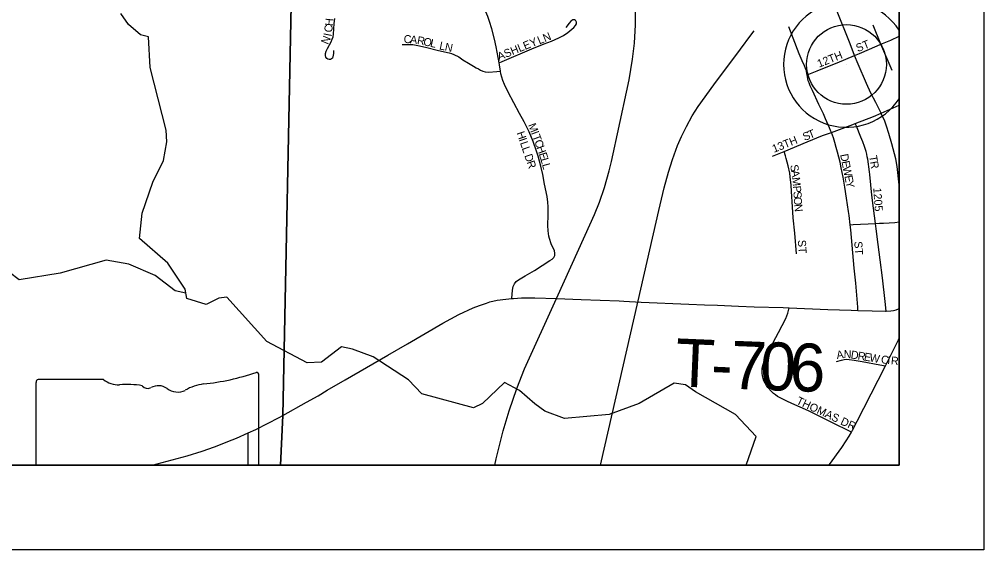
# Model space of a CAD drawing. Extents: x 0 to 34, y 0 to 22.
# Drawn here: x 29.776 to 30.917, y 14 to 14.628 of the extents above; entities that cross this region are included whole.
import ezdxf

# ---------------------------------------------------------------- set-up
doc = ezdxf.new("R2010")
doc.units = 0
for name, color, linetype in [('GM_X_Adjacent_County', 7, 'Continuous'), ('GM_X_County', 7, 'Continuous'), ('GM_X_County_Road', 7, 'Continuous'), ('GM_X_Minor_River', 7, 'Continuous'), ('GM_X_Rail_Line', 7, 'Continuous'), ('GM_X_State_Route', 7, 'Continuous'), ('GM_X_State_Shield', 7, 'Continuous'), ('GM_X_Township', 7, 'Continuous'), ('GM_X_Township_Road', 7, 'Continuous'), ('GM_X_Township_Road_Text', 7, 'Continuous'), ('GM_X_Township_Subdivision', 7, 'Continuous'), ('GM_X_Township_Subdivision_Text', 7, 'Continuous'), ('GM_X_Unincorporated', 7, 'Continuous'), ('GM_X_Unincorporated_Location', 7, 'Continuous'), ('SH_Data', 7, 'Continuous')]:
    doc.layers.add(name, color=color, linetype=linetype)

msp = doc.modelspace()

# ---------------------------------------------------------------- linework, layer by layer
at = {"layer": 'GM_X_Adjacent_County'}
msp.add_lwpolyline([(24.0167, 18.0693), (24.0167, 14.1), (30.8167, 14.1), (30.8167, 17.8174)], dxfattribs=at)
at = {"layer": 'GM_X_County'}
msp.add_lwpolyline([(24.0167, 18.0693), (24.0167, 14.1), (30.8167, 14.1), (30.8167, 17.8174)], dxfattribs=at)
at = {"layer": 'GM_X_County_Road'}
msp.add_lwpolyline([(30.3383, 14.1), (30.3399, 14.1076), (30.3447, 14.1267), (30.3482, 14.1407), (30.3517, 14.1524), (30.3553, 14.1645), (30.3644, 14.1909), (30.3735, 14.214), (30.4111, 14.2976)], dxfattribs=at)
at = {"layer": 'GM_X_Minor_River'}
for points in [[(30.6355, 14.1), (30.6473, 14.1342), (30.6229, 14.1599), (30.5758, 14.187), (30.564, 14.1953), (30.5504, 14.1971), (30.5091, 14.1731), (30.4736, 14.16), (30.4209, 14.1552), (30.3974, 14.1639), (30.3856, 14.1729), (30.3677, 14.1884), (30.3498, 14.1978), (30.3238, 14.173), (30.3132, 14.168), (30.2521, 14.1845), (30.2361, 14.2011), (30.1943, 14.2282), (30.17, 14.2376), (30.1571, 14.2402), (30.1333, 14.2219), (30.1162, 14.2214), (30.0687, 14.2467), (30.0215, 14.2988), (30.0117, 14.298), (29.9969, 14.2903), (29.9741, 14.2975), (29.9722, 14.3085), (29.9516, 14.3391), (29.9181, 14.3685), (29.921, 14.3985), (29.9337, 14.435), (29.9465, 14.4608), (29.9505, 14.4829), (29.9497, 14.4965), (29.9308, 14.5708), (29.9287, 14.6072), (29.9193, 14.6094), (29.9048, 14.6219), (29.896, 14.6348)], [(29.973, 14.3039), (29.9601, 14.3065), (29.9365, 14.3246), (29.9053, 14.3381), (29.8784, 14.3426), (29.8243, 14.3275), (29.7758, 14.3197), (29.7294, 14.3544)]]:
    msp.add_lwpolyline(points, dxfattribs=at)
at = {"layer": 'GM_X_Rail_Line'}
for points in [[(30.4634, 14.1), (30.5079, 14.2945), (30.5323, 14.4017), (30.5388, 14.4286), (30.5437, 14.4471), (30.5484, 14.4618), (30.5543, 14.4784), (30.559, 14.4892), (30.565, 14.5011), (30.5717, 14.5137), (30.5788, 14.5246), (30.5973, 14.5505), (30.6288, 14.5926), (30.6412, 14.609)], [(30.6412, 14.609), (30.6453, 14.6143)]]:
    msp.add_lwpolyline(points, dxfattribs=at)
at = {"layer": 'GM_X_State_Route'}
for points in [[(30.4111, 14.2976), (30.4452, 14.3722), (30.4562, 14.3969), (30.4622, 14.4113), (30.4682, 14.429), (30.4734, 14.4484), (30.4762, 14.4596), (30.4783, 14.4687), (30.4836, 14.4925), (30.4972, 14.5564), (30.5013, 14.5809), (30.5034, 14.5995), (30.5047, 14.6212), (30.5048, 14.6282), (30.5049, 14.6344), (30.5048, 14.6424), (30.5046, 14.6482), (30.5042, 14.6545), (30.5035, 14.6656), (30.5035, 14.6658)], [(30.2117, 14.2302), (30.235, 14.2436), (30.2767, 14.2683), (30.2958, 14.2786), (30.3128, 14.2863), (30.3202, 14.2891), (30.3286, 14.292), (30.3323, 14.2933), (30.3411, 14.2953), (30.3515, 14.2966), (30.3586, 14.2974), (30.3606, 14.2976), (30.3697, 14.2981), (30.3857, 14.2983), (30.4111, 14.2976)], [(30.0275, 14.1299), (30.0328, 14.1321), (30.0467, 14.1383), (30.0555, 14.1423), (30.0832, 14.1565), (30.0875, 14.1589), (30.1157, 14.1747), (30.1293, 14.1821), (30.1398, 14.1887), (30.1613, 14.2013), (30.2117, 14.2302)], [(29.933, 14.1), (29.9743, 14.1113), (29.9921, 14.1167), (30.0069, 14.1217), (30.0275, 14.1299)]]:
    msp.add_lwpolyline(points, dxfattribs=at)
at = {"layer": 'GM_X_State_Shield'}
for p, q in [((30.0592, 14.1018), (30.0592, 14.2065)), ((30.0592, 14.2065), (30.0592, 14.2065)), ((29.7981, 14.2015), (29.7981, 14.2015)), ((29.7955, 14.1), (30.0589, 14.1))]:
    msp.add_line(p, q, dxfattribs=at)
for points in [[(29.7955, 14.1981), (29.7955, 14.1981), (29.7955, 14.1)], [(29.8754, 14.2015), (29.8754, 14.2015), (29.7981, 14.2015)], [(30.0592, 14.1018), (30.0592, 14.1018), (30.0592, 14.1018)]]:
    msp.add_lwpolyline(points, dxfattribs=at)
for centre, radius, start, end in [((29.9653, 14.4744), 0.2796, 275.8445, 288.9065), ((30.0563, 14.2069), 0.00294, 351.8621, 97.738), ((29.7986, 14.1985), 0.00305, 98.1301, 188.1301), ((29.8937, 14.2248), 0.0296, 231.6195, 271.1119), ((29.9036, 14.0892), 0.1064, 80.4867, 94.9883), ((29.9277, 14.1995), 0.00855, 219.7921, 297.1024), ((29.9403, 14.1764), 0.0178, 54.4667, 119.1411), ((30.001, 14.1404), 0.0563, 97.3462, 120.7689), ((29.9632, 14.2081), 0.0214, 233.8562, 294.8282), ((30.0561, 14.1014), 0.00314, 333.7254, 7.7341)]:
    msp.add_arc(centre, radius, start, end, dxfattribs=at)
at = {"layer": 'GM_X_Township'}
msp.add_line((26.1244, 14.1), (30.0847, 14.1), dxfattribs=at)
for points in [[(30.0847, 14.1), (30.8167, 14.1), (30.8167, 15.629)], [(30.0983, 14.6841), (30.0875, 14.1589), (30.0847, 14.1)], [(30.0847, 14.1), (30.0875, 14.1589), (30.0983, 14.6841)]]:
    msp.add_lwpolyline(points, dxfattribs=at)
at = {"layer": 'GM_X_Township_Road'}
for points in [[(30.4111, 14.2976), (30.4406, 14.2962), (30.4856, 14.2945), (30.4909, 14.2943)], [(30.4909, 14.2943), (30.5114, 14.2932), (30.5678, 14.2908), (30.5863, 14.29), (30.6018, 14.2895), (30.6266, 14.2884), (30.6452, 14.2876), (30.6793, 14.2867), (30.6866, 14.2864)], [(30.6866, 14.2864), (30.7321, 14.2845), (30.76, 14.2835), (30.7679, 14.2832)], [(30.8014, 14.2825), (30.8067, 14.2827), (30.8099, 14.2832), (30.813, 14.284), (30.816, 14.285), (30.8167, 14.2853)], [(30.7679, 14.2832), (30.7848, 14.2827), (30.8004, 14.2824), (30.8014, 14.2825)], [(30.8005, 14.2178), (30.8013, 14.2194), (30.8158, 14.2485), (30.8167, 14.2503)], [(30.7601, 14.1393), (30.7614, 14.1417), (30.7669, 14.1522), (30.775, 14.1677), (30.8005, 14.2178)], [(30.7335, 14.1), (30.7343, 14.101), (30.7488, 14.1212), (30.7539, 14.1288), (30.7574, 14.1344), (30.7601, 14.1393)]]:
    msp.add_lwpolyline(points, dxfattribs=at)
at = {"layer": 'GM_X_Township_Subdivision'}
for points in [[(30.3433, 14.5763), (30.3398, 14.5954), (30.3379, 14.6045), (30.3348, 14.6165), (30.3321, 14.6253), (30.33, 14.6311), (30.3275, 14.6366), (30.3232, 14.6447), (30.3124, 14.6631), (30.3069, 14.6722)], [(30.7638, 14.5852), (30.7634, 14.5863), (30.7578, 14.6008), (30.7433, 14.6373), (30.7386, 14.6484), (30.7379, 14.6501)], [(30.1474, 14.5911), (30.1474, 14.5873), (30.1471, 14.5853), (30.1468, 14.5835), (30.1462, 14.5821), (30.1453, 14.5811), (30.1439, 14.5804), (30.1423, 14.5802), (30.1408, 14.5807), (30.1396, 14.5816), (30.1385, 14.5831), (30.1379, 14.5849), (30.138, 14.5874), (30.1389, 14.5903), (30.1403, 14.5932), (30.1448, 14.6014), (30.146, 14.6043), (30.1469, 14.6072), (30.1474, 14.6103), (30.1479, 14.6166), (30.1484, 14.6228), (30.1489, 14.629)], [(30.3433, 14.5763), (30.3471, 14.5779), (30.3821, 14.5928), (30.3966, 14.5987), (30.4053, 14.6022), (30.4139, 14.6059), (30.4194, 14.6089), (30.4246, 14.6123), (30.4296, 14.6162), (30.4319, 14.6183), (30.4339, 14.6207), (30.4348, 14.6224), (30.435, 14.6237), (30.435, 14.6246), (30.4347, 14.6254), (30.4343, 14.6261), (30.4337, 14.6266), (30.4327, 14.6272), (30.4317, 14.6273), (30.431, 14.6273), (30.4303, 14.6272), (30.4293, 14.6267), (30.4282, 14.6256), (30.4262, 14.6232), (30.4224, 14.6181)], [(30.7077, 14.5623), (30.7076, 14.5632), (30.7069, 14.5668), (30.7059, 14.5697), (30.7047, 14.5727), (30.7021, 14.5786), (30.6985, 14.5872), (30.686, 14.6189)], [(30.795, 14.5984), (30.7857, 14.6211)], [(30.795, 14.5984), (30.8066, 14.6033), (30.8167, 14.6078)], [(30.2288, 14.5983), (30.2382, 14.5983), (30.2413, 14.598), (30.2474, 14.597), (30.2565, 14.5948), (30.2716, 14.591), (30.2842, 14.5884), (30.2871, 14.5875), (30.2898, 14.5862), (30.2958, 14.5834), (30.3005, 14.5801), (30.307, 14.5761), (30.3131, 14.5723), (30.3163, 14.5705), (30.3189, 14.5692), (30.3212, 14.5679), (30.324, 14.5665), (30.327, 14.5656), (30.3309, 14.5655), (30.3409, 14.5662), (30.345, 14.5665)], [(30.7638, 14.5852), (30.7697, 14.5876), (30.7906, 14.5965), (30.795, 14.5984)], [(30.8082, 14.5673), (30.795, 14.5984)], [(30.7077, 14.5623), (30.7138, 14.5647), (30.7196, 14.567), (30.7282, 14.5705), (30.7433, 14.5766), (30.7638, 14.5852)], [(30.7953, 14.5168), (30.789, 14.5296), (30.7833, 14.5406), (30.7781, 14.5519), (30.7681, 14.5747), (30.7638, 14.5852)], [(30.345, 14.5665), (30.3437, 14.5741), (30.3433, 14.5763)], [(30.3586, 14.2974), (30.3592, 14.3071), (30.3602, 14.3118), (30.3615, 14.3149), (30.3637, 14.3174), (30.3662, 14.3194), (30.3742, 14.3244), (30.3851, 14.3306), (30.4036, 14.3422), (30.4061, 14.344), (30.4081, 14.346), (30.4093, 14.3484), (30.4095, 14.351), (30.4088, 14.3537), (30.405, 14.3623), (30.4031, 14.3683), (30.4023, 14.3714), (30.4014, 14.3776), (30.4012, 14.3839), (30.4013, 14.3964), (30.4013, 14.4061), (30.401, 14.4115), (30.4002, 14.4182), (30.3972, 14.4328), (30.395, 14.4444), (30.3929, 14.454), (30.3895, 14.4661), (30.3877, 14.4719), (30.3836, 14.4833), (30.3788, 14.4946), (30.3729, 14.5064), (30.3677, 14.5166), (30.3543, 14.5416), (30.3498, 14.5508), (30.3478, 14.5556), (30.3456, 14.5633), (30.345, 14.5665)], [(30.7366, 14.4939), (30.7356, 14.4963), (30.7343, 14.4996), (30.7294, 14.5103), (30.727, 14.5159), (30.7218, 14.5269), (30.7141, 14.5438), (30.7113, 14.5493), (30.71, 14.5526), (30.7092, 14.555), (30.7086, 14.5579), (30.7077, 14.5623)], [(30.7953, 14.5168), (30.8167, 14.5262)], [(30.7647, 14.5045), (30.7861, 14.5128), (30.7953, 14.5168)], [(30.8167, 14.4305), (30.8165, 14.432), (30.8142, 14.4535), (30.8126, 14.4627), (30.8113, 14.4687), (30.8081, 14.4807), (30.8043, 14.4926), (30.8016, 14.5014), (30.7995, 14.5073), (30.7958, 14.5157), (30.7953, 14.5168)], [(30.7366, 14.4939), (30.762, 14.5034), (30.7647, 14.5045)], [(30.7887, 14.3863), (30.7863, 14.4043), (30.7845, 14.4197), (30.7833, 14.4319), (30.7821, 14.4442), (30.7817, 14.4472), (30.7794, 14.4622), (30.7789, 14.4652), (30.7783, 14.4683), (30.7776, 14.4713), (30.7758, 14.4772), (30.7735, 14.4829), (30.7712, 14.4884), (30.766, 14.5014), (30.7647, 14.5045)], [(30.6805, 14.4716), (30.7079, 14.483), (30.7261, 14.4902), (30.7366, 14.4939)], [(30.7588, 14.3848), (30.7577, 14.3956), (30.7569, 14.4006), (30.7543, 14.4161), (30.7522, 14.4291), (30.7503, 14.4411), (30.7481, 14.452), (30.7467, 14.459), (30.7454, 14.4649), (30.7438, 14.4706), (30.7422, 14.4763), (30.7406, 14.482), (30.7388, 14.4877), (30.7366, 14.4939)], [(30.6668, 14.4661), (30.6805, 14.4716)], [(30.6952, 14.3501), (30.6932, 14.3746), (30.6914, 14.3931), (30.6906, 14.4058), (30.6894, 14.4241), (30.6889, 14.4316), (30.6878, 14.4414), (30.6872, 14.4456), (30.6852, 14.4546), (30.6829, 14.4633), (30.682, 14.4665), (30.6805, 14.4716)], [(30.7887, 14.3863), (30.7935, 14.3866), (30.7981, 14.3867), (30.8116, 14.3875), (30.8167, 14.388)], [(30.7588, 14.3848), (30.7623, 14.385), (30.7887, 14.3863)], [(30.7679, 14.2832), (30.7678, 14.287), (30.7654, 14.3154), (30.7635, 14.3334), (30.7594, 14.3788), (30.7588, 14.3848)], [(30.8014, 14.2825), (30.8001, 14.2939), (30.7969, 14.3217), (30.7943, 14.343), (30.7919, 14.3613), (30.7896, 14.3798), (30.7887, 14.3863)], [(30.7601, 14.1393), (30.7538, 14.1423), (30.7426, 14.1477), (30.7261, 14.1563), (30.7093, 14.1643), (30.6895, 14.1733), (30.6839, 14.176), (30.6782, 14.1785), (30.6728, 14.1815), (30.6702, 14.1832), (30.6678, 14.1851), (30.6655, 14.1873), (30.6614, 14.192), (30.6596, 14.1945), (30.658, 14.1971), (30.6567, 14.1999), (30.6557, 14.2029), (30.6549, 14.2059), (30.6545, 14.2089), (30.6544, 14.212), (30.6546, 14.2151), (30.6553, 14.2181), (30.6572, 14.224), (30.6584, 14.2269), (30.661, 14.2325), (30.6739, 14.2573), (30.6782, 14.2656), (30.6824, 14.2738), (30.6837, 14.2767), (30.6851, 14.2802), (30.6859, 14.2834), (30.6866, 14.2864)], [(30.7424, 14.223), (30.7483, 14.2246), (30.7514, 14.2252), (30.7544, 14.2254), (30.7575, 14.2253), (30.7636, 14.2245), (30.7727, 14.2228), (30.7939, 14.219), (30.8005, 14.2178)], [(30.0467, 14.1), (30.0467, 14.1259), (30.0467, 14.1383)]]:
    msp.add_lwpolyline(points, dxfattribs=at)
at = {"layer": 'GM_X_Unincorporated'}
msp.add_line((30.8167, 14.534), (30.8167, 14.6151), dxfattribs=at)
msp.add_circle((30.7543, 14.5745), 0.0472, dxfattribs=at)
msp.add_arc((30.7543, 14.5745), 0.0744, 33.0244, 326.9756, dxfattribs=at)
at = {"layer": 'GM_X_Unincorporated_Location'}
msp.add_line((30.7543, 14.5745), (30.7543, 14.5745), dxfattribs=at)
at = {"layer": 'SH_Data'}
for points in [[(23.9167, 21), (30.9167, 21), (30.9167, 14), (23.9167, 14)], [(24.0167, 20.9), (30.8167, 20.9), (30.8167, 14.1), (24.0167, 14.1)]]:
    msp.add_lwpolyline(points, close=True, dxfattribs=at)

# ---------------------------------------------------------------- texts
at = {"layer": 'GM_X_Township_Road_Text'}
for s, rotation, p in [('T', 357.5642, (30.5509, 14.1935)), ('7', 357.7227, (30.6165, 14.1907)), ('0', 357.9204, (30.6514, 14.1893)), ('6', 357.9485, (30.6862, 14.1881)), ('-', 357.5799, (30.5933, 14.1917))]:
    msp.add_text(s, height=0.0568, rotation=rotation, dxfattribs=at).set_placement(p)
at = {"layer": 'GM_X_Township_Subdivision_Text'}
for s, rotation, p in [('H', 84.2823, (30.1467, 14.6196)), ('C', 83.5474, (30.1458, 14.612)), ('N', 67.2204, (30.141, 14.5974)), ('I', 78.871, (30.1449, 14.6071)), ('C', 357.8792, (30.2304, 14.5999)), ('A', 353.6375, (30.2377, 14.5997)), ('R', 349.3958, (30.2458, 14.5988)), ('O', 347.275, (30.2531, 14.5974)), ('L', 347.275, (30.2612, 14.5956)), ('ASHLEY', 22.3806, (30.3435, 14.579)), ('LN', 22.3821, (30.391, 14.5981)), ('ST', 21.8039, (30.7677, 14.589)), ('L', 348.5561, (30.2721, 14.5924)), ('N', 347.9358, (30.2786, 14.5911)), ('12TH', 21.8039, (30.7219, 14.5706)), ('M', 290.3706, (30.3775, 14.5029)), ('H', 288.7598, (30.364, 14.4935)), ('I', 290.3885, (30.381, 14.4936)), ('T', 290.401, (30.3825, 14.4896)), ('13TH', 21.8039, (30.6686, 14.4698)), ('S', 22.603, (30.7049, 14.4838)), ('T', 21.1925, (30.711, 14.4864)), ('I', 288.7391, (30.3667, 14.4857)), ('L', 288.7623, (30.368, 14.4817)), ('C', 290.3628, (30.3848, 14.4834)), ('H', 290.0802, (30.3874, 14.4764)), ('L', 288.7718, (30.3701, 14.4754)), ('D', 288.7863, (30.3731, 14.4667)), ('E', 287.3377, (30.3902, 14.4687)), ('D', 281.1085, (30.7468, 14.4677)), ('T', 278.7482, (30.781, 14.4661)), ('R', 289.1206, (30.3758, 14.4588)), ('L', 285.7728, (30.3922, 14.4624)), ('L', 285.6601, (30.394, 14.456)), ('S', 280.0776, (30.6876, 14.4551)), ('E', 281.1063, (30.7484, 14.4595)), ('R', 280.5042, (30.7821, 14.4592)), ('A', 277.9384, (30.6888, 14.4487)), ('W', 281.1106, (30.7497, 14.4529)), ('M', 276.2235, (30.6899, 14.4405)), ('E', 281.1116, (30.7518, 14.4423)), ('Y', 281.7594, (30.7531, 14.4357)), ('P', 274.1012, (30.691, 14.4306)), ('S', 273.9104, (30.6915, 14.424)), ('1205', 273.9426, (30.786, 14.4283)), ('O', 273.9313, (30.6919, 14.4173)), ('N', 275.6198, (30.6925, 14.4087)), ('ST', 273.5882, (30.6968, 14.3666)), ('ST', 273.5738, (30.7635, 14.3649)), ('A', 8.2012, (30.7431, 14.2257)), ('N', 357.8797, (30.7509, 14.2269)), ('D', 350.8683, (30.7589, 14.2266)), ('R', 350.5816, (30.7671, 14.2253)), ('E', 350.5601, (30.7745, 14.2241)), ('W', 350.6568, (30.7811, 14.223)), ('C', 353.4768, (30.7948, 14.2208)), ('I', 354.071, (30.8023, 14.2199)), ('R', 354.0879, (30.8065, 14.2195)), ('THOMAS DR', 335.0269, (30.6941, 14.1731))]:
    msp.add_text(s, height=0.00947, rotation=rotation, dxfattribs=at).set_placement(p)

doc.saveas('drawing.dxf')
